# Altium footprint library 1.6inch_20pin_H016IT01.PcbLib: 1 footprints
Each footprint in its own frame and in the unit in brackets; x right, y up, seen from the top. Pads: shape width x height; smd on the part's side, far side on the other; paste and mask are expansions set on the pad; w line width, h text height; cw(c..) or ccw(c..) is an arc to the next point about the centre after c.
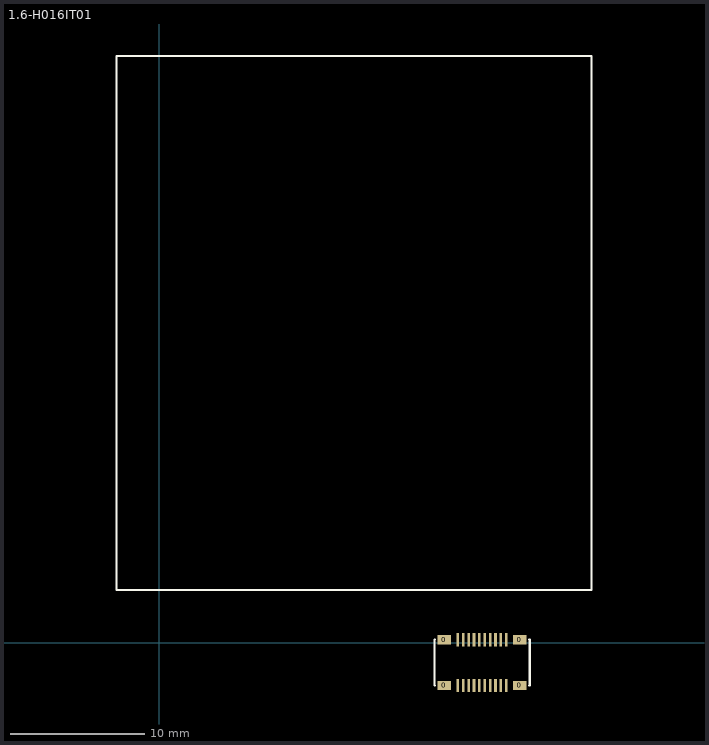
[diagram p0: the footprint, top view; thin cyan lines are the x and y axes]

## 1.6-H016IT01 [mm] "1.6 TFT LCD"
pads (24):
  rect 1x0.7 smd: 0(21.265,-3.196) 0(21.265,0.214) 0(26.876,-3.196) 0(26.876,0.214)
  rect 0.2x1 smd: 1(22.27,0.214) 2(22.67,0.214) 3(23.07,0.214) 4(23.47,0.214) 5(23.87,0.214) 6(24.27,0.214) 7(24.67,0.214) 8(25.07,0.214) 9(25.47,0.214) 10(25.87,0.214) 11(25.87,-3.196) 12(25.47,-3.196) 13(25.07,-3.196) 14(24.67,-3.196) 15(24.27,-3.196) 16(23.87,-3.196) 17(23.47,-3.196) 18(23.07,-3.196) 19(22.67,-3.196) 20(22.27,-3.196)
Top Overlay:
  lines w0.152: 20.565,-3.196 20.515,-3.196 20.515,0.214 20.565,0.214 ; 27.575,-3.196 27.625,-3.196 27.625,0.214 27.575,0.214 ; -3.175,3.937 -3.175,43.737 32.225,43.737 32.225,3.937 -3.175,3.937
